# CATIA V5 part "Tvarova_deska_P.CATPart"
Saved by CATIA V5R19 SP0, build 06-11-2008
Part number: Tvarova_deska_P
Source: Unknown
Bounding box of the stored display mesh (mm): x -55 to 55, y -75 to 75, z -40 to 0
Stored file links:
  C:\Users\jsmid\Desktop\DP_Smidak_Forma LEGO\Tvarova_deska_P.CATPart
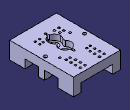
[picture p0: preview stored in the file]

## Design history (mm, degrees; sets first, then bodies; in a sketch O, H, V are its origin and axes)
Body1 (main body)
  Solid1 "PartBody": solid without history
  Sketch1 on face of Solid1, origin (55, 0, 0), H (0, 1, 0), V (0, 0, 1)
    point P1 (-23, -35.9222)
    line L1 (-7, -28) -> (-7, -43.8443)
    line L2 (-7, -43.8443) -> (-39, -43.8443)
    line L3 (-39, -43.8443) -> (-39, -28)
    line L4 (-39, -28) -> (-7, -28)
    point P2 (-7, -28)
    reference projected arc E1 centre (-15, -28) radius 8 from (-15, -36) to (-15, -20) ccw from edge [face of Solid1 | face of Solid1]
    reference projected arc E2 centre (-31, -28) radius 8 from (-31, -20) to (-31, -36) ccw from edge [face of Solid1 | face of Solid1]
    reference projected arc E3 centre (-15, -28) radius 8 from (-15, -36) to (-15, -20) ccw from edge [face of Solid1 | face of Solid1]
    point P6 (23, -35.6121)
    line L5 (39, -28) -> (39, -43.2243)
    line L6 (39, -43.2243) -> (7, -43.2243)
    line L7 (7, -43.2243) -> (7, -28)
    line L8 (7, -28) -> (39, -28)
    point P7 (39, -28)
    reference projected arc E4 centre (31, -28) radius 8 from (31, -36) to (31, -20) ccw from edge [face of Solid1 | face of Solid1]
    reference projected arc E5 centre (15, -28) radius 8 from (15, -20) to (15, -36) ccw from edge [face of Solid1 | face of Solid1]
    reference projected arc E6 centre (31, -28) radius 8 from (31, -36) to (31, -20) ccw from edge [face of Solid1 | face of Solid1]
    vertical: L1 V, L3 V, L5 V, L7 V
    horizontal: L2 H, L4 H, L6 H, L8 H
    equidistance: L1 L3 P1, L2 L4 P1, L5 L7 P6, L6 L8 P6
    tangency: L1 E1, L3 E2, L5 E4, L7 E5
    coincidence: P2 E3, P7 E6
  Pocket1: profile Sketch1, direction (-1, 0, 0), length 20
  Sketch2 on face of Solid1, origin (-55, 0, 0), H (0, -1, 0), V (0, 0, 1)
    point P1 (-23, -35.2187)
    line L1 (-7, -28) -> (-7, -42.4373)
    line L2 (-7, -42.4373) -> (-39, -42.4373)
    line L3 (-39, -42.4373) -> (-39, -28)
    line L4 (-39, -28) -> (-7, -28)
    point P2 (-7, -28)
    reference projected arc E1 centre (-15, -28) radius 8 from (-15, -36) to (-15, -20) ccw from edge [face of Solid1 | face of Solid1]
    reference projected arc E2 centre (-31, -28) radius 8 from (-31, -20) to (-31, -36) ccw from edge [face of Solid1 | face of Solid1]
    reference projected arc E3 centre (-15, -28) radius 8 from (-15, -36) to (-15, -20) ccw from edge [face of Solid1 | face of Solid1]
    point P6 (23, -35.7565)
    line L5 (39, -28) -> (39, -43.5131)
    line L6 (39, -43.5131) -> (7, -43.5131)
    line L7 (7, -43.5131) -> (7, -28)
    line L8 (7, -28) -> (39, -28)
    point P7 (39, -28)
    reference projected arc E4 centre (31, -28) radius 8 from (31, -36) to (31, -20) ccw from edge [face of Solid1 | face of Solid1]
    reference projected arc E5 centre (15, -28) radius 8 from (15, -20) to (15, -36) ccw from edge [face of Solid1 | face of Solid1]
    reference projected arc E6 centre (31, -28) radius 8 from (31, -36) to (31, -20) ccw from edge [face of Solid1 | face of Solid1]
    vertical: L1 V, L3 V, L5 V, L7 V
    horizontal: L2 H, L4 H, L6 H, L8 H
    equidistance: L1 L3 P1, L2 L4 P1, L5 L7 P6, L6 L8 P6
    tangency: L1 E1, L3 E2, L5 E4, L7 E5
    coincidence: P2 E3, P7 E6
  Pocket2: profile Sketch2, direction (1, 0, 0), length 20
  Sketch3 on face of Solid1, origin (55, 0, 0), H (0, 1, 0), V (0, 0, 1)
    line L1 (7, -49.3212) -> (39, -49.3212)
    line L2 (39, -49.3212) -> (39, -20)
    line L3 (39, -20) -> (7, -20)
    line L4 (7, -20) -> (7, -49.3212)
    reference projected line E1 (15, -20) -> (31, -20) from edge [face of Solid1 | face of Solid1]
    reference projected line E2 (39, -40) -> (39, -28) from edge [face of Solid1 | face of Pocket1 from Sketch1.L5]
    reference projected line E3 (7, -28) -> (7, -40) from edge [face of Solid1 | face of Pocket1 from Sketch1.L7]
    line L5 (-39, -43.4551) -> (-7, -43.4551)
    line L6 (-7, -43.4551) -> (-7, -20)
    line L7 (-7, -20) -> (-39, -20)
    line L8 (-39, -20) -> (-39, -43.4551)
    reference projected line E4 (-31, -20) -> (-15, -20) from edge [face of Solid1 | face of Solid1]
    reference projected line E5 (-7, -40) -> (-7, -28) from edge [face of Solid1 | face of Pocket1 from Sketch1.L1]
    reference projected line E6 (-39, -28) -> (-39, -40) from edge [face of Solid1 | face of Pocket1 from Sketch1.L3]
    horizontal: L1 H, L3 H, L5 H, L7 H
    vertical: L2 V, L4 V, L6 V, L8 V
    coincidence: L3 E1, L2 E2, L4 E3, L7 E4, L6 E5, L8 E6
  Pocket3: profile Sketch3, direction (-1, 0, 0), length 20
  Sketch4 on face of Solid1, origin (-55, 0, 0), H (0, -1, 0), V (0, 0, 1)
    line L1 (7, -45.0625) -> (39, -45.0625)
    line L2 (39, -45.0625) -> (39, -20)
    line L3 (39, -20) -> (7, -20)
    line L4 (7, -20) -> (7, -45.0625)
    reference projected line E1 (39, -40) -> (39, -28) from edge [face of Solid1 | face of Pocket2 from Sketch2.L5]
    reference projected line E2 (7, -28) -> (7, -40) from edge [face of Solid1 | face of Pocket2 from Sketch2.L7]
    reference projected line E3 (31, -20) -> (15, -20) from edge [face of Solid1 | face of Solid1]
    line L5 (-39, -42.0206) -> (-7, -42.0206)
    line L6 (-7, -42.0206) -> (-7, -20)
    line L7 (-7, -20) -> (-39, -20)
    line L8 (-39, -20) -> (-39, -42.0206)
    reference projected line E4 (-15, -20) -> (-31, -20) from edge [face of Solid1 | face of Solid1]
    reference projected line E5 (-7, -40) -> (-7, -28) from edge [face of Solid1 | face of Pocket2 from Sketch2.L1]
    reference projected line E6 (-39, -28) -> (-39, -40) from edge [face of Solid1 | face of Pocket2 from Sketch2.L3]
    horizontal: L1 H, L3 H, L5 H, L7 H
    vertical: L2 V, L4 V, L6 V, L8 V
    coincidence: L2 E1, L4 E2, L3 E3, L7 E4, L6 E5, L8 E6
  Pocket4: profile Sketch4, direction (1, 0, 0), length 20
